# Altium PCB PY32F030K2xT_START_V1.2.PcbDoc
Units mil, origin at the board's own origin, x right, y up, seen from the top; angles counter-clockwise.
Board outline 1183.03 x 2496.24 mil, 2 copper layers (Top Layer, Bottom Layer); 35 components, 40 nets, 165 pads, 10 vias.
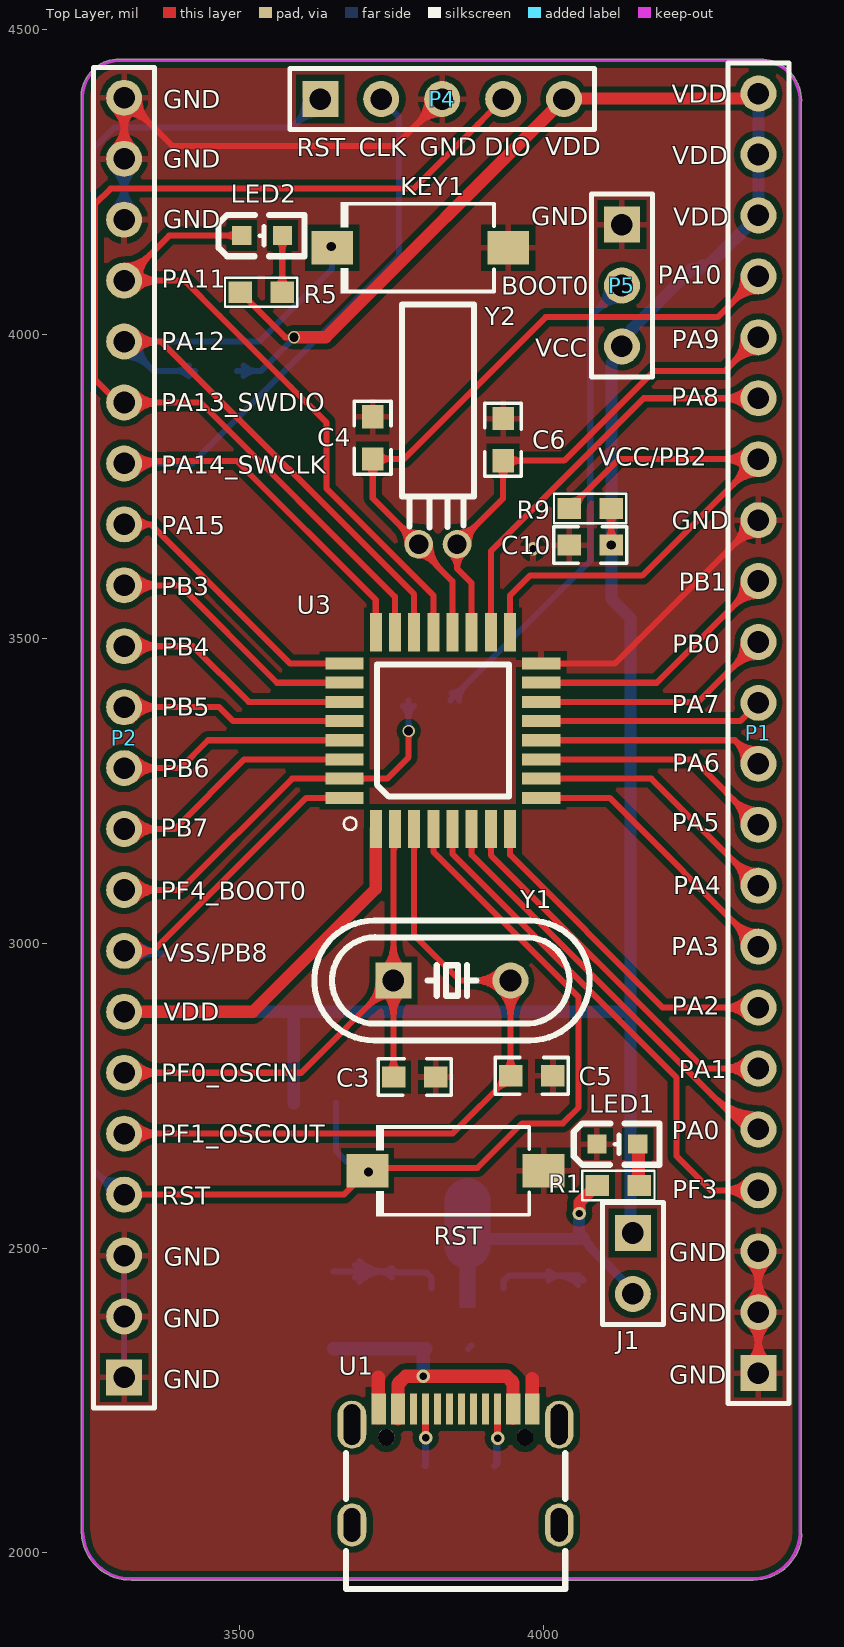
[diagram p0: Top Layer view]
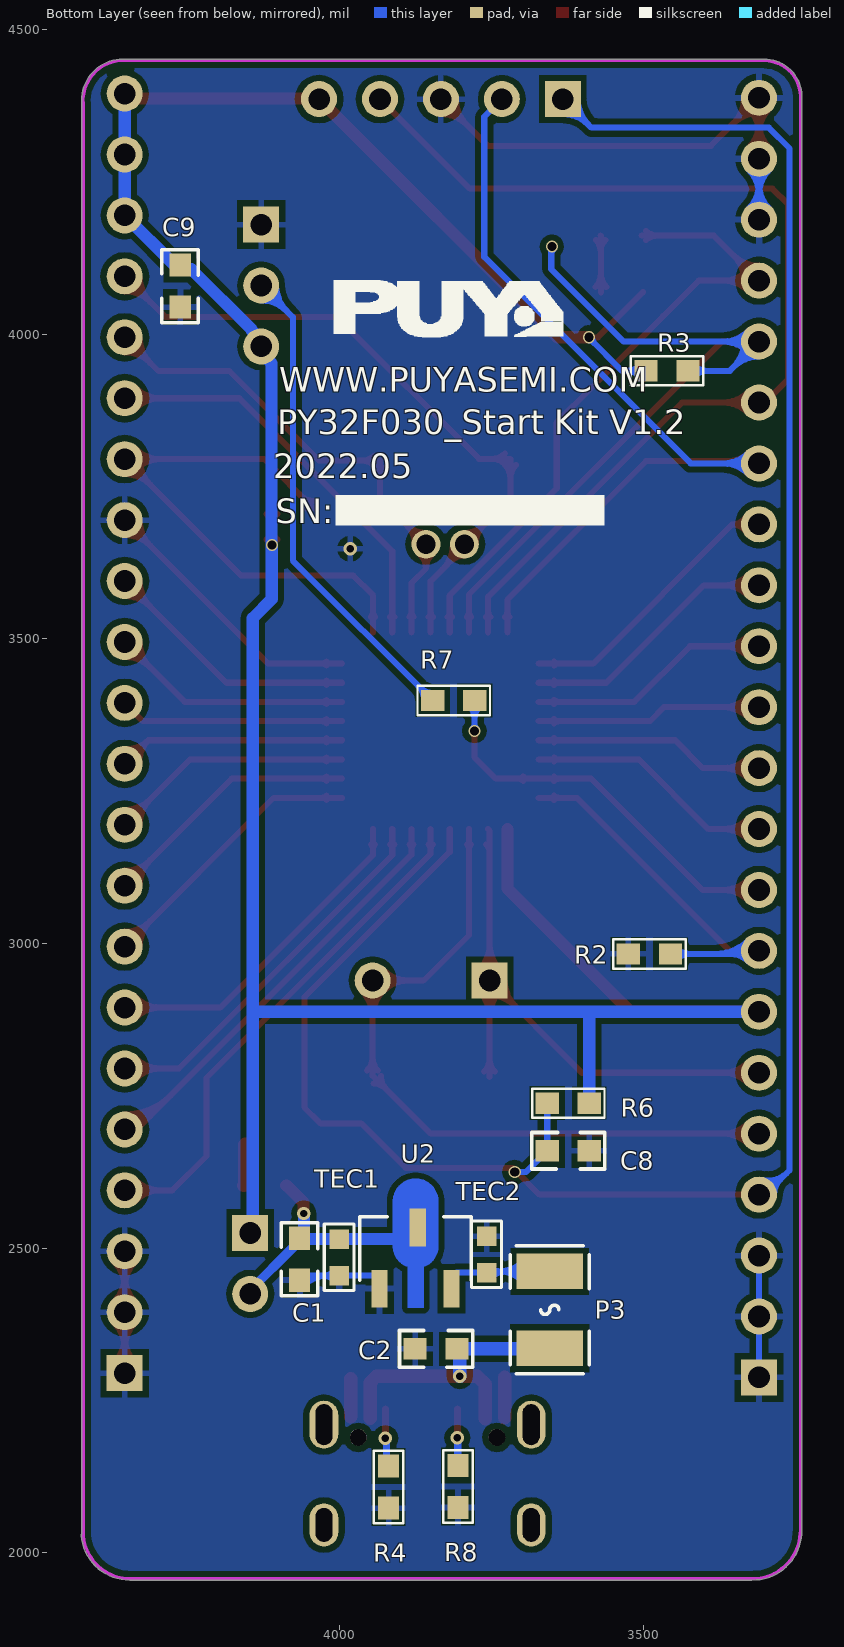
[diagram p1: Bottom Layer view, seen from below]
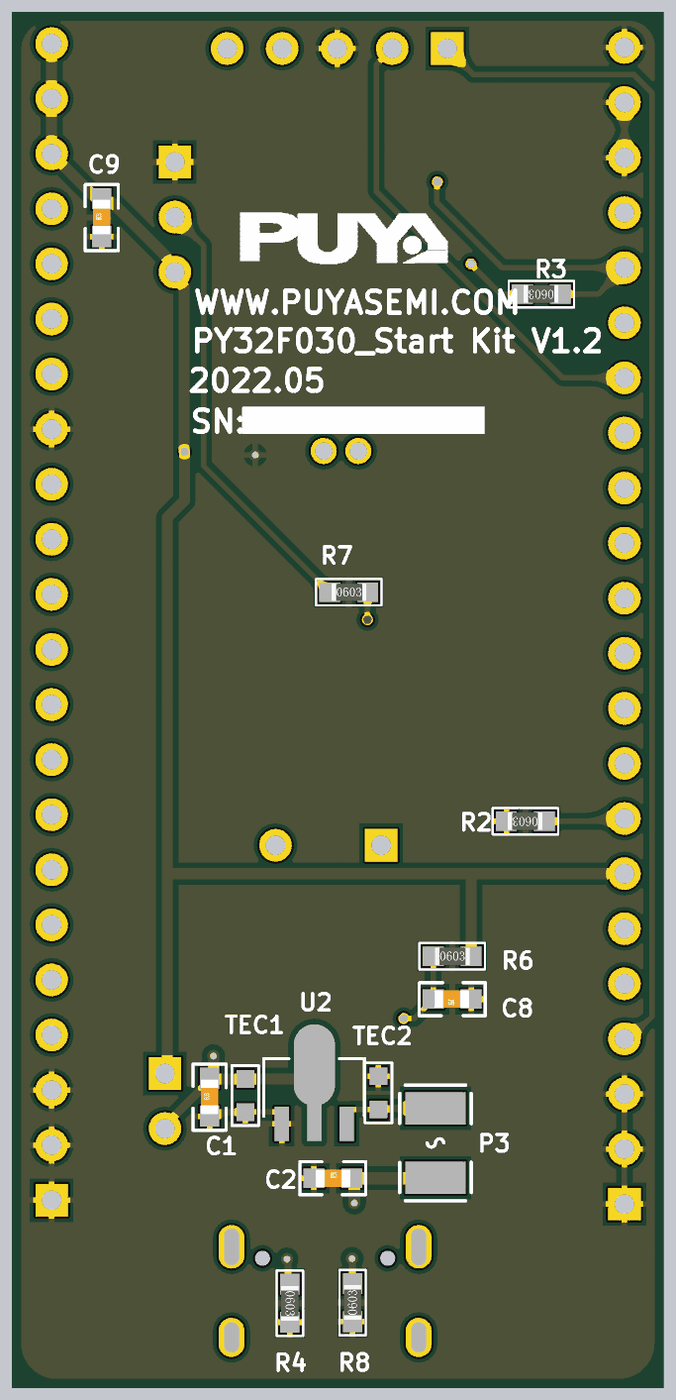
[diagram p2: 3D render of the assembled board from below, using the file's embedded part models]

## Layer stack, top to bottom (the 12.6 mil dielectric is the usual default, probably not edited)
Top Solder: solder mask 0.4, Solder Resist, Dk 3.5
Top Layer: signal copper 1.4
Dielectric1: dielectric 12.6, FR-4, Dk 4.8
Bottom Layer: signal copper 1.4
Bottom Solder: solder mask 0.4, Solder Resist, Dk 3.5

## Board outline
3240.49,4390 cw(c3243,4390) 3240.49,4390.02 3240.49,4391 cw(c3243,4391) 3240.51,4391.36 cw(c3302.5,4389.5) 3303.01,4451.52 cw(c3302.5,4389.5) 3303.02,4451.51 3303,4451.52 4360,4451.52 cw(c4360,4449) 4360.21,4451.51 cw(c4354.5,4383.5) 4422.75,4383.5 cw(c4354.5,4383.5) 4422.52,4377.9 4422.52,2031.01 cw(c4421,2029) 4423.52,2029 cw(c4421,2029) 4423.51,2028.79 cw(c4343.5,2035.5) 4336.9,1955.48 3323.21,1955.48 cw(c3323,1957.99) 3323.07,1955.48 cw(c3320.96,2035.24) 3241.27,2031.38 cw(c3243,2033.2) 3240.49,2033.2

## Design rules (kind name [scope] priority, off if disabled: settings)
Clearance Clearance_8 [InNamedPolygon('Bottom Layer-No Net')] p1: gap=10 ignorepadtopadclearanceinfootprint=FALSE
Clearance Clearance_7 [InNamedPolygon('Top Layer-No Net')] p2: gap=10 ignorepadtopadclearanceinfootprint=FALSE
Clearance Clearance_6 [InNamedPolygon('Bottom Layer-No Net')] p3: gap=10 ignorepadtopadclearanceinfootprint=FALSE
Clearance Clearance_5 [InNamedPolygon('Bottom Layer-No Net')] p4: gap=10 ignorepadtopadclearanceinfootprint=FALSE
Clearance Clearance_4 [InNamedPolygon('Bottom Layer-No Net')] p5: gap=15 ignorepadtopadclearanceinfootprint=FALSE
Clearance Clearance_3 [InNamedPolygon('Bottom Layer-No Net')] p6: gap=15 ignorepadtopadclearanceinfootprint=FALSE
Clearance Clearance_2 [InNamedPolygon('Bottom Layer-No Net')] p7: gap=10 ignorepadtopadclearanceinfootprint=FALSE
Clearance Clearance_1 [InNamedPolygon('Bottom Layer-No Net')] p8: gap=10 ignorepadtopadclearanceinfootprint=FALSE except(0: Arc-Hole Track-Hole SMDPad-Hole THPad-Hole Via-Hole Fill-Hole Poly-Hole Region-Hole Text-Hole)
Clearance [All] p9: gap=6 ignorepadtopadclearanceinfootprint=FALSE
MinimumSolderMaskSliver [All] p1: minsoldermaskwidth=0
PolygonConnect [All] p1: connectstyle=Relief reliefconductorwidth=10 reliefentries=4 polygonreliefangle="90 Angle" airgapwidth=10
RoutingVias [All] p1: holewidth=20 width=30 viastyle="Through Hole" minholewidth=5 minwidth=10 maxholewidth=28 maxwidth=50
SilkToSilkClearance [All] p1: silktosilkclearance=0
SilkToSolderMaskClearance SilkscreenOverComponentPads [IsPad] p1: minsilkscreentomaskgap=10 clearancetoexposedcopper=TRUE
SolderMaskExpansion [All] p1: expansion=4 istentingtop=FALSE
Width [All] p1: maxlimit=100 minlimit=10 preferedwidth=12
27 further rules are at their usual default settings.

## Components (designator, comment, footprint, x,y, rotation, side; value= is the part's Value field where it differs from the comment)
C1 "0.1uF/50V" 0603C 4065,2482 r90 bottom
C2 "0.1uF/50V" 0603C 3841,2335 r180 bottom value=2.2uF
C3 "22pF" 0603C 3788,2781 r180 top
C4 "12.5pF" 0603C 3719,3830 r270 top
C5 "22pF" 0603C 3980,2783 r0 top
C6 "12.5pF" 0603C 3933,3827 r90 top
C8 "0.1uF/50V" 0603C 3624,2660 r0 bottom value=2.2uF
C9 "0.1uF/50V" 0603C 4261,4079 r90 bottom value=2.2uF
C10 "0.1uF/50V" 0603C 4076,3654 r0 top value=2.2uF
J1 "JUMP" HDR1X2 4146,2525 r270 top
KEY1 "1TS002B-2600-5001" SW 3844,4143 r180 top
LED1 "RED" 0603_LED 4135,2670 r0 top
LED2 "GREEN" 0603_LED 3552,4161 r0 top
P1 "Header 22" HDR1X22 4352,2295 r90 top
P2 "Header 22" HDR1X22 3311,2288 r90 top
P3 "SMD1210P005TF" SDM1210P005TF 3676,2396 r90 bottom
P4 "Debug" HDR1X5 3633,4386 r0 top
P5 "Header 3" HDR1X3 4128,4180 r270 top
R1 "470Ω" 0603R 4122,2602 r0 top value=10K
R2 "0" 0603R 3491,2984 r0 bottom value=10K
R3 "1.5K" 0603R 3462,3941 r0 bottom value=10K
R4 "5.1K" 0603R 3920,2108 r270 bottom value=10K
R5 "680Ω" 0603R 3536,4068 r0 top value=10K
R6 "10K" 0603R 3624,2737 r180 bottom
R7 "10K" 0603R 3812,3398 r180 bottom
R8 "5.1K" 0603R 3804,2109 r90 bottom value=10K
R9 "0" 0603R 4076,3713 r0 top value=10K
RST "1TS002B-2600-5001" SW 3902,2628 r180 top
TEC1 "10uF" 0603 4000,2485 r90 bottom value=10uF/16V
TEC2 "10uF" 0603 3758,2490 r270 bottom value=10uF/16V
U1 "KH-TYPE-C-16P" USB-C-SMD_KH-TYPE-C-16P 3855,2141 r0 top
U2 "LM1117-3.3" LM1117-3.3 3933.9,2433.62 r270 bottom
U3 "PY32F030" LQFP32 3724,3188 r90 top
Y1 "24M" 25MHZ_2 3883,2936 r0 top value=X503225MSB2GI
Y2 "32.768KHz" 32768KHZ_2 3822,3779 r270 top value=X503225MSB2GI

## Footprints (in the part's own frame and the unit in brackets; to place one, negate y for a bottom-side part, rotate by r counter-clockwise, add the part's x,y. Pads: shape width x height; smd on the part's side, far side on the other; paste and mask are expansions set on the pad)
25MHZ_2 [mm]
  rect 1.5x1.5 hole 0.9: 1(-3.302,0.087)
  round 1.5 hole 0.9: 2(1.578,0.087)
  silkscreen extent -6.6,-2.41 4.88,2.59
0603 [mil]
  rect 32x32 smd: 1(30,0) 2(-30,0)
  silkscreen extent -54,-25 55,25
0603_LED [mil]
  rect 31.5x31.5 smd: 1(19,1) 2(-48,1)
  silkscreen extent -86,-33 55,35
0603C [mil]
  rect 38x35 smd: 1(-34.5,0) 2(34.5,0)
  silkscreen extent -60,-30 60,30, body extent -31,-16 32,16, height 12
0603R [mil]
  rect 38x35 smd: 1(-34.5,1) 2(34.5,1)
  silkscreen extent -59,-23 59,25, body extent -31,-15 32,17, height 18
32768KHZ_2 [mm]
  round 1.2 hole 0.8: 1(3.142,0.903) 2(3.142,-0.697)
  silkscreen extent -6.86,-1.4 2.44,1.6
HDR1X2 [mm] "Connector; Header; 2 Position"
  rect 1.5x1.5 hole 0.9: 1(0,0)
  round 1.5 hole 0.9: 2(2.54,0)
  silkscreen extent -1.27,-1.27 3.81,1.27
HDR1X3 [mm] "Connector; Header; 3 Position"
  rect 1.5x1.5 hole 0.9: 1(0,0)
  round 1.5 hole 0.9: 2(2.54,0) 3(5.08,0)
  silkscreen extent -1.27,-1.27 6.35,1.27
HDR1X5 [mm] "Connector; Header; 5 Position"
  rect 1.5x1.5 hole 0.9: 1(0,0)
  round 1.5 hole 0.9: 2(2.54,0) 3(5.08,0) 4(7.62,0) 5(10.16,0)
  silkscreen extent -1.27,-1.27 11.43,1.27
HDR1X22 [mm] "Connector; Header; 22 Position"
  rect 1.5x1.5 hole 0.9: 1(0,0)
  round 1.5 hole 0.9: 2(2.54,0) 3(5.08,0) 4(7.62,0) 5(10.16,0) 6(12.7,0) 7(15.24,0) 8(17.78,0) 9(20.32,0) 10(22.86,0) 11(25.4,0) 12(27.94,0) 13(30.48,0) 14(33.02,0) 15(35.56,0) 16(38.1,0) 17(40.64,0) 18(43.18,0) 19(45.72,0) 20(48.26,0) 21(50.8,0) 22(53.34,0)
  silkscreen extent -1.27,-1.27 54.61,1.27
LM1117-3.3 [mm]
  rect 1.575x0.672 smd: 1(0,0) 2(-2.55,1.598) 3(0,3)
  Top Layer region: -3.64,2.459 -1.785,2.459 -1.741,2.458 -1.696,2.455 -1.652,2.449 -1.608,2.442 -1.565,2.433 -1.522,2.421 -1.479,2.408 -1.437,2.393 -1.396,2.375 -1.356,2.356 -1.317,2.335 -1.279,2.312 -1.241,2.288 -1.206,2.261 -1.171,2.233 -1.138,2.204 -1.106,2.173 -1.075,2.14 -1.047,2.106 -1.019,2.071 -0.994,2.034 -0.97,1.996 -0.948,1.958 -0.928,1.918 -0.91,1.839 0.788,1.839 0.788,1.179 -0.91,1.179 -0.928,1.099 -0.948,1.06 -0.97,1.021 -0.994,0.983 -1.019,0.947 -1.047,0.911 -1.075,0.877 -1.106,0.845 -1.138,0.814 -1.171,0.784 -1.206,0.756 -1.241,0.73 -1.279,0.705 -1.317,0.682 -1.356,0.661 -1.396,0.642 -1.437,0.625 -1.479,0.609 -1.522,0.596 -1.565,0.585 -1.608,0.575 -1.652,0.568 -1.696,0.563 -1.741,0.56 -1.785,0.559 -3.64,0.559 -3.684,0.56 -3.728,0.563 -3.773,0.568 -3.817,0.575 -3.86,0.585 -3.903,0.596 -3.946,0.609 -3.988,0.625 -4.029,0.642 -4.069,0.661 -4.108,0.682 -4.146,0.705 -4.183,0.73 -4.219,0.756 -4.254,0.784 -4.287,0.814 -4.319,0.845 -4.349,0.877 -4.378,0.911 -4.405,0.947 -4.431,0.983 -4.455,1.021 -4.477,1.06 -4.497,1.099 -4.515,1.14 -4.531,1.181 -4.546,1.224 -4.558,1.266 -4.568,1.31 -4.577,1.353 -4.583,1.398 -4.587,1.442 -4.589,1.486 -4.589,1.531 -4.587,1.575 -4.583,1.62 -4.577,1.664 -4.568,1.708 -4.558,1.751 -4.546,1.794 -4.531,1.836 -4.515,1.877 -4.497,1.918 -4.477,1.958 -4.455,1.996 -4.431,2.034 -4.405,2.071 -4.378,2.106 -4.349,2.14 -4.319,2.173 -4.287,2.204 -4.254,2.233 -4.219,2.261 -4.183,2.288 -4.146,2.312 -4.108,2.335 -4.069,2.356 -4.029,2.375 -3.988,2.393 -3.946,2.408 -3.903,2.421 -3.86,2.433 -3.817,2.442 -3.773,2.449 -3.728,2.455 -3.684,2.458
  silkscreen extent -3.01,-0.83 -0.35,3.83
LQFP32 [mil]
  rect 63x19.7 smd: 1(0,0) 2(0,-31.5) 3(0,-63) 4(0,-94.5) 5(0,-125.9) 6(0,-157.4) 7(0,-188.9) 8(0,-220.4) 17(322.8,-220.4) 18(322.8,-188.9) 19(322.8,-157.4) 20(322.8,-125.9) 21(322.8,-94.5) 22(322.8,-63) 23(322.8,-31.5) 24(322.8,0)
  rect 19.7x63 smd: 9(51.2,-271.6) 10(82.7,-271.6) 11(114.2,-271.6) 12(145.7,-271.6) 13(177.1,-271.6) 14(208.6,-271.6) 15(240.1,-271.6) 16(271.6,-271.6) 25(271.6,51.2) 26(240.1,51.2) 27(208.6,51.2) 28(177.1,51.2) 29(145.7,51.2) 30(114.2,51.2) 31(82.7,51.2) 32(51.2,51.2)
  silkscreen extent -2,-218 270,52, body extent -15,-286 339,68, height 63
SDM1210P005TF [mm]
  rect 1.485x2.781 smd: 1(-1.524,-0.549) 2(1.676,-0.549)
  silkscreen extent -2.59,-2.2 2.74,1.1
SW [mm]
  rect 1.74x1.4 smd: 1(-2.476,0.024) 2(4.864,0.024)
  silkscreen extent -1.88,-1.88 4.5,1.93
USB-C-SMD_KH-TYPE-C-16P [mm] "https://item.szlcsc.com/747093.html"
  oval 1.2x2 hole 0.7 slot 1.7 at 90 deg: 1(-4.32,1.765) 2(4.32,1.765)
  oval 1.2x1.8 hole 0.7 slot 1.4 at 90 deg: 3(-4.32,-2.415) 4(4.32,-2.415)
  rect 0.3x1.3 smd: A1(-3.35,2.415) A4(-2.55,2.415) A5(-1.25,2.415) A6(-0.25,2.415) A7(0.25,2.415) A8(1.25,2.415) A9(2.55,2.415) A12(3.35,2.415) B1(3.05,2.415) B4(2.25,2.415) B5(1.75,2.415) B6(0.75,2.415) B7(-0.75,2.415) B8(-1.75,2.415) B9(-2.25,2.415) B12(-3.05,2.415)
  round 0.7 hole 0.7 unplated: ""(-2.89,1.235) ""(2.89,1.235)
  silkscreen extent -4.57,-5.08 4.57,0.57

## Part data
C1 C3 C4 C5 C6: library part Cap, "Capacitor"
C2 C8 C9 C10: library part CAP, "Capacitor"
KEY1 RST: BOM_JLCPCB Part Class="Extended Part", BOM_Manufacturer=HYP
LED1 LED2: library part PDI-E803_Dup1
P1 P2: "Header, 22-Pin"
P4: library part CON5
P5: "Header, 3-Pin"
R1 R2 R3 R5 R6 R7 R9: library part Res, "Resistor"
R4 R8: library part Res_1, "Resistor"
TEC1 TEC2: library part 贴片钽电容
U1: BOM_JLCPCB Part Class="Extended Part", BOM_Manufacturer="Shenzhen Kinghelm Elec"
Y1 Y2: library part CRYSTAL, "Crystal"

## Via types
v1: diameter 22, hole 12, Top Layer to Bottom Layer, tented both sides, 5 vias
v2: diameter 20, hole 15, Top Layer to Bottom Layer, 5 vias

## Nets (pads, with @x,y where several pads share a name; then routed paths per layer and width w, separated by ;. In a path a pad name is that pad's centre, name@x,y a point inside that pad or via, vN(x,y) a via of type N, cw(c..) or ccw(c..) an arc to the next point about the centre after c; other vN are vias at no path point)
BOOT0: P2.9 R7.2 U3.31 | length 920.7
  Top Layer w10: P2.9 3404,3088 3586.7,3270.7 U3.31 3742.7,3270.7 3778,3306 v2(3778,3349) ; P2.9@3321.27,3077.73 cw(c3346.07,3052.93) 3346.07,3088 cw(c3346.07,3123.07) P2.9@3321.27,3098.27 ; P2.9@3328.34,3070.66 cw(c3370.21,3028.79) 3370.21,3088 cw(c3370.21,3147.21) P2.9@3328.34,3105.34 ; U3.31@3647.72,3267.27 ccw(c3639.44,3258.99) 3639.44,3270.7 ccw(c3639.44,3282.41) U3.31@3647.72,3274.13 ; U3.31@3697.88,3267.27 cw(c3706.16,3258.99) 3706.16,3270.7 cw(c3706.16,3282.41) U3.31@3697.88,3274.13 ; v2@3774.46,3345.46 cw(c3765.93,3336.93) 3778,3336.93 cw(c3790.07,3336.93) v2@3781.54,3345.46
  Bottom Layer w10: R7.2@3768.66,3390.16 cw(c3746.12,3367.62) 3778,3367.62 ; v2@3774.46,3352.54 ccw(c3765.93,3361.07) 3778,3361.07 ccw(c3790.07,3361.07) v2@3781.54,3352.54 ; R7.2 3778,3398.5 v2(3778,3349) ; 3778,3370.03 cw(c3806.47,3370.03) R7.2@3786.34,3390.16
GND: C1.1 C2.1 C3.1 C4.1 C5.2 C6.2 C8.1 C9.1 C10.1 KEY1.1 LED1.2 P1.1 P1.2 P1.3 P1.15 P2.1 P2.2 P2.3 P2.20 P2.21 P2.22 P4.3 P5.1 R2.2 R4.2 R8.1 RST.1 TEC1.2 TEC2.2 U1.A1 U1.A12 U1.B1 U1.B12 U2.1 U3.16 | length 3682.9
  Top Layer w10: P2.21@3293.66,4305.34 ccw(c3251.79,4347.21) 3311,4347.21 ccw(c3370.21,4347.21) P2.21@3328.34,4305.34 ; P2.22@3293.66,4370.66 cw(c3251.79,4328.79) 3311,4328.79 cw(c3370.21,4328.79) P2.22@3328.34,4370.66 ; P2.21@3300.73,4298.27 ccw(c3275.93,4323.07) 3311,4323.07 ccw(c3346.07,4323.07) P2.21@3321.27,4298.27 ; P2.22@3300.73,4377.73 cw(c3275.93,4352.93) 3311,4352.93 cw(c3346.07,4352.93) P2.22@3321.27,4377.73 ; P2.21 P2.22 3390,4309 3756,4309 P4.3 ; P2.22@3311,4363.47 cw(c3311,4304.26) 3352.87,4346.13 cw(c3394.74,4388) P2.22@3335.53,4388 ; P2.22@3311,4373.47 cw(c3311,4338.4) 3335.8,4363.2 cw(c3360.6,4388) P2.22@3325.53,4388 ; P4.3@3808.47,4386 cw(c3749.26,4386) 3791.13,4344.13 cw(c3833,4302.26) P4.3@3833,4361.47 ; P4.3@3818.47,4386 cw(c3783.4,4386) 3808.2,4361.2 cw(c3833,4336.4) P4.3@3833,4371.47 ; U3.16 4116.6,3459.6 P1.15 ; U3.16@4020.68,3456.17 cw(c4028.96,3447.89) 4028.96,3459.6 cw(c4028.96,3471.31) U3.16@4020.68,3463.03 ; P1.15@4327.47,3695 cw(c4268.26,3695) 4310.13,3653.13 cw(c4352,3611.26) P1.15@4352,3670.47 ; P1.1@4334.66,2312.34 ccw(c4292.79,2354.21) 4352,2354.21 ccw(c4411.21,2354.21) P1.1@4369.34,2312.34 ; P1.2@4334.66,2377.66 cw(c4292.79,2335.79) 4352,2335.79 cw(c4411.21,2335.79) P1.2@4369.34,2377.66 ; P1.2@4334.66,2412.34 ccw(c4292.79,2454.21) 4352,2454.21 ccw(c4411.21,2454.21) P1.2@4369.34,2412.34 ; P1.3@4334.66,2477.66 cw(c4292.79,2435.79) 4352,2435.79 cw(c4411.21,2435.79) P1.3@4369.34,2477.66 ; P1.15@4337.47,3695 cw(c4302.4,3695) 4327.2,3670.2 cw(c4352,3645.4) P1.15@4352,3680.47 ; P1.1@4341.73,2305.27 ccw(c4316.93,2330.07) 4352,2330.07 ccw(c4387.07,2330.07) P1.1@4362.27,2305.27 ; P1.2@4341.73,2384.73 cw(c4316.93,2359.93) 4352,2359.93 cw(c4387.07,2359.93) P1.2@4362.27,2384.73 ; P1.2@4341.73,2405.27 ccw(c4316.93,2430.07) 4352,2430.07 ccw(c4387.07,2430.07) P1.2@4362.27,2405.27 ; P1.3@4341.73,2484.73 cw(c4316.93,2459.93) 4352,2459.93 cw(c4387.07,2459.93) P1.3@4362.27,2484.73 ; P1.1 P1.2 P1.3
  Top Layer w22: U1.A1@3728,2222 3728,2288 ; U1.A12@3981,2223 3981,2286
  Bottom Layer w10: P2.20@3293.66,4205.34 ccw(c3251.79,4247.21) 3311,4247.21 ccw(c3370.21,4247.21) P2.20@3328.34,4205.34 ; P2.21@3293.66,4270.66 cw(c3251.79,4228.79) 3311,4228.79 cw(c3370.21,4228.79) P2.21@3328.34,4270.66 ; P2.20@3300.73,4198.27 ccw(c3275.93,4223.07) 3311,4223.07 ccw(c3346.07,4223.07) P2.20@3321.27,4198.27 ; P2.21@3300.73,4277.73 cw(c3275.93,4252.93) 3311,4252.93 cw(c3346.07,4252.93) P2.21@3321.27,4277.73 ; P2.1@3311,2278 P2.3@3311,2478 ; P2.20 P2.21 ; R2.2@3522,2979.5 R2.2 ; C2.1 C2.1@3881,2340.5 ; U2.1 3933.9,2446.77 3942.13,2455 TEC1.2 4057.5,2455 C1.1 ; TEC1.2@4007.78,2447.22 cw(c4026.56,2428.44) 4026.56,2455 cw(c4026.56,2481.56) TEC1.2@4007.78,2462.78 ; 4020.34,2455 cw(c4020.34,2404.34) C1.1@4056.16,2440.16 ; 4044.48,2455 cw(c4044.48,2428.48) C1.1@4063.23,2447.23
  other v1: 3982,3648
MCU_RST: C8.2 P2.4 P4.1 R6.1 RST.2 U3.4 | length 3911.5
  Top Layer w10: P2.4 3671.47,2588 RST.2 ; v2(3712,2625) RST.2@3715.54,2625 ; RST.2@3712,2628.53 3715.47,2632 3891,2632 3964,2705 4031,2705 4057,2731 4057,2912 3818.5,3150.5 3818.5,3162.92 U3.4
  Bottom Layer w10: 3266,2623 ccw(c3295.63,2652.63) P2.4@3305.33,2611.86 ; 3276.2,2612.8 cw(c3251.4,2588) P2.4@3286.47,2588 ; 3278.66,2610.34 ccw(c3300.5,2632.18) P2.4@3307.64,2602.13 ; P2.4@3311,2578 3261,2628 3261,4305 3295,4339 3586,4339 P4.1 ; P4.1@3608.47,4386 cw(c3549.26,4386) 3591.13,4344.13 cw(c3633,4302.26) P4.1@3633,4361.47 ; P4.1@3618.47,4386 cw(c3583.4,4386) 3608.2,4361.2 cw(c3633,4336.4) P4.1@3633,4371.47 ; R6.1 C8.2 3693.5,2625 v2(3712,2625)
MCU_VDD: C9.2 C10.2 J1.1 P1.20 P1.21 P1.22 P2.7 P4.5 P5.3 R3.2 R5.1 R6.2 R9.2 U3.1 | length 4993
  Top Layer w10: R5.1 3575.5,3995 v2(3590,3995) ; C10.2@4101.66,3662.84 ccw(c4080.32,3684.18) 4110.5,3684.18 ccw(c4140.68,3684.18) C10.2@4119.34,3662.84 ; R9.2@4101.66,3705.16 cw(c4080.32,3683.82) 4110.5,3683.82 cw(c4140.68,3683.82) R9.2@4119.34,3705.16 ; C10.2@4106.96,3657.54 ccw(c4098.43,3666.07) 4110.5,3666.07 ccw(c4122.57,3666.07) C10.2@4114.04,3657.54 ; v2(4110.5,3654) R9.2
  Top Layer w20: P2.7 3522,2888 3724,3090 U3.1 ; v2(3590,3995) 3642,3995 P4.5 4034,4387 4333.43,4387 4341.43,4395 P1.22
  Bottom Layer w10: R3.2 3536,3940 3590,3994 v2(3590,3995) ; R3.2@3506.84,3931.16 cw(c3528.18,3909.82) 3528.18,3940 cw(c3528.18,3970.18) R3.2@3506.84,3948.84 ; 3580.76,3984.76 ccw(c3570.51,3995) v2@3585,3995 ; 3583.17,3987.17 cw(c3590,3980.34) v2@3590,3990 ; C9.2@4248.5,4101 4254.25,4106.75 C9.2@4255.25,4107.75 ; C9.2 C9.2@4270.5,4113.5
  Bottom Layer w20: P2.7 3589.5,2888 ; R6.2 3589.5,2888 ; J1.1@4142,2515 4142,2888 ; C9.2@4254.25,4106.75 4242.75,4106.75 4144.09,4008.09 4144.09,4006.66 4128,3990.57 P5.3 4128,3969.43 4111,3952.43 4111,3654.5 v2(4110.5,3654) 4110.67,3653.83 4110.67,3565.33 4142,3534 4142,2888 ; C9.2@4255.25,4107.75 C9.2 ; C9.2@4270.5,4113.5 P1.20 P1.21 P1.22 ; 3589.5,2888 4142,2888
NetC1_2: C1.2 J1.2 R1.1 TEC1.1 U2.2 | length 433.3
  Top Layer w20: v1(4058,2557) 4058.38,2557.38 4058.38,2575.38 4086,2603 R1.1
  Bottom Layer w15: C1.2 4065,2512 4068,2512 4075,2505 4075,2502 4146,2431 J1.2
  Bottom Layer w20: U2.2 3871,2518.23 3874.23,2515 TEC1.1 C1.2@4057.5,2515 ; v1(4058,2557) 4057.5,2556.5 4057.5,2524 C1.2
NetLED1_1: LED1.1 R1.2 | length 69
  Top Layer w22: LED1.1 4155.25,2669.75 4155.25,2604.25 R1.2
NetLED2_1: LED2.1 R5.2 | length 181.4
  Top Layer w10: R5.2@3561.66,4077.84 ccw(c3540.32,4099.18) 3570.5,4099.18 ccw(c3600.68,4099.18) R5.2@3579.34,4077.84 ; LED2.1@3563.4,4154.4 cw(c3546.26,4137.26) 3570.5,4137.26 ; R5.2 3570.5,4161.5 LED2.1 ; 3570.5,4134.84 cw(c3598.16,4134.84) LED2.1@3578.6,4154.4
NetP3_2: P3.2 TEC2.1 U2.3 | length 371.1
  Bottom Layer w10: P3.2 3756.02,2461.98 TEC2.1 3807.18,2460 3815.79,2451.39 U2.3 ; P3.2@3689.97,2451.92 cw(c3714.27,2427.62) 3714.27,2461.98 cw(c3714.27,2496.34) P3.2@3689.97,2472.05 ; P3.2@3697.04,2444.85 cw(c3738.41,2403.48) 3738.41,2461.98 cw(c3738.41,2520.49) P3.2@3697.04,2479.12 ; 3726.65,2461.98 cw(c3726.65,2428.65) TEC2.1@3750.22,2452.22 ; 3736.23,2461.98 ccw(c3736.23,2481.77) TEC2.1@3750.22,2467.78
NetP5_2: P5.2 R7.1 | length 993.1
  Bottom Layer w10: R7.1 4076,3628.5 4076,4028 P5.2 ; R7.1@3848,3411.5 ccw(c3848,3438.06) 3866.78,3419.28 ; R7.1@3860.5,3399 cw(c3894.3,3399) 3870.4,3422.9 ; P5.2@4103.47,4080 cw(c4044.26,4080) 4086.13,4038.13 cw(c4128,3996.26) P5.2@4128,4055.47 ; P5.2@4113.47,4080 cw(c4078.4,4080) 4103.2,4055.2 cw(c4128,4030.4) P5.2@4128,4065.47
NetR4_1: R4.1 U1.B5 | length 98.9
  Top Layer w12: U1.B5 3923.9,2188.21 3924,2188.11 v1@3924,2185
  Bottom Layer w12: R4.1 3922.42,2145.92 3922.42,2186.2 v1(3924.33,2188.11)
NetR8_2: R8.2 U1.A5 | length 93.1
  Top Layer w10: v1@3805.79,2189.21 v1(3806,2189)
  Top Layer w12: v1@3805.79,2189.21 U1.A5
  Bottom Layer w12: R8.2 3805.5,2144 3805.5,2188.5 v1(3806,2189)
OSC32IN: C4.2 P1.19 U3.20 Y2.2 | length 1519.5
  Top Layer w10: C4.2@3710.16,3785.16 cw(c3688.82,3763.82) 3719,3763.82 cw(c3749.18,3763.82) C4.2@3727.84,3785.16 ; C4.2@3727.84,3786.66 cw(c3749.18,3765.32) 3749.18,3795.5 cw(c3749.18,3825.68) C4.2@3727.84,3804.34 ; Y2.2@3775.93,3655.3 ccw(c3730.97,3655.3) 3762.76,3687.09 ccw(c3794.55,3718.88) Y2.2@3794.55,3673.92 ; Y2.2@3794.55,3636.68 cw(c3794.55,3604.12) 3817.57,3627.14 ; Y2.2@3794.55,3650.16 3849.9,3594.82 U3.20 ; Y2.2 3719,3730.85 C4.2 3770.5,3795.5 4003,4028 4285,4028 P1.19 ; Y2.2@3803.17,3655.3 ccw(c3836.39,3655.3) 3812.9,3631.81 ; Y2.2@3813.17,3655.3 ccw(c3870.53,3655.3) 3829.97,3614.74 ; U3.20@3846.47,3535.88 ccw(c3838.19,3544.16) 3849.9,3544.16 ccw(c3861.61,3544.16) U3.20@3853.33,3535.88 ; P1.19@4327.47,4095 cw(c4268.26,4095) 4310.13,4053.13 cw(c4352,4011.26) P1.19@4352,4070.47 ; P1.19@4337.47,4095 cw(c4302.4,4095) 4327.2,4070.2 cw(c4352,4045.4) P1.19@4352,4080.47
OSC32OUT: C6.1 P1.18 U3.19 Y2.1 | length 1215.9
  Top Layer w10: Y2.1@3845.6,3641.01 cw(c3824.23,3615.46) 3857.54,3615.46 ; Y2.1@3857.54,3673.92 ccw(c3857.54,3718.88) 3889.33,3687.09 ccw(c3921.12,3655.3) Y2.1@3876.17,3655.3 ; Y2.1@3869.49,3641.01 ccw(c3890.86,3615.46) 3857.54,3615.46 ; U3.19@3877.97,3535.88 ccw(c3869.69,3544.16) 3881.4,3544.16 ccw(c3893.11,3544.16) U3.19@3884.83,3535.88 ; U3.19 3881.4,3591.6 3857.54,3615.46 ; C6.1@3924.16,3782.16 cw(c3902.82,3760.82) 3933,3760.82 cw(c3963.18,3760.82) C6.1@3941.84,3782.16 ; C6.1@3941.84,3783.66 cw(c3963.18,3762.32) 3963.18,3792.5 cw(c3963.18,3822.68) C6.1@3941.84,3801.34 ; P1.18@4327.47,3995 cw(c4268.26,3995) 4310.13,3953.13 cw(c4352,3911.26) P1.18@4352,3970.47 ; P1.18@4337.47,3995 cw(c4302.4,3995) 4327.2,3970.2 cw(c4352,3945.4) P1.18@4352,3980.47 ; P1.18 4296.53,3939.53 4180.03,3939.53 4033,3792.5 C6.1 3933,3730.76 Y2.1 3857.54,3615.46
OSCIN: C3.2 P2.6 U3.2 Y1.1 | length 1568.7
  Top Layer w10: P2.6 3601.59,2788 Y1.1 ; P2.6@3321.27,2777.73 cw(c3346.07,2752.93) 3346.07,2788 cw(c3346.07,2823.07) P2.6@3321.27,2798.27 ; P2.6@3328.34,2770.66 cw(c3370.21,2728.79) 3370.21,2788 cw(c3370.21,2847.21) P2.6@3328.34,2805.34 ; Y1.1@3728.21,2914.62 ccw(c3703.41,2939.43) Y1.1@3738.49,2939.43 ; Y1.1@3728.21,2914.63 cw(c3753.01,2889.82) Y1.1@3753.01,2924.9 ; Y1.1@3728.49,2939.43 cw(c3669.27,2939.43) 3711.14,2897.55 cw(c3753.01,2855.68) Y1.1@3753.01,2914.9 ; Y1.1@3735.67,2922.08 cw(c3693.8,2880.21) 3753.01,2880.21 cw(c3812.23,2880.21) Y1.1@3770.36,2922.08 ; Y1.1@3735.67,2956.77 ccw(c3693.8,2998.64) 3753.01,2998.64 ccw(c3812.23,2998.64) Y1.1@3770.36,2956.77 ; Y1.1@3742.74,2929.15 cw(c3717.94,2904.35) 3753.01,2904.35 cw(c3788.09,2904.35) Y1.1@3763.29,2929.15 ; Y1.1@3742.74,2949.7 ccw(c3717.94,2974.5) 3753.01,2974.5 ccw(c3788.09,2974.5) Y1.1@3763.29,2949.7 ; C3.2@3744.66,2789.84 ccw(c3724.5,2810) 3753.01,2810 ; 3753.01,2812.35 ccw(c3784.85,2812.35) C3.2@3762.34,2789.84 ; 3753.01,3148.64 cw(c3773.21,3148.64) U3.2@3758.93,3162.92 ; C3.2 3753.01,2781.49 Y1.1 ; U3.2 3753.01,3185.51 Y1.1
OSCOUT: C5.1 P2.5 U3.3 Y1.2 | length 1750.8
  Top Layer w10: P2.5 3849.78,2688 C5.1@3945.14,2783.36 ; P2.5@3321.27,2677.73 cw(c3346.07,2652.93) 3346.07,2688 cw(c3346.07,2723.07) P2.5@3321.27,2698.27 ; P2.5@3328.34,2670.66 cw(c3370.21,2628.79) 3370.21,2688 cw(c3370.21,2747.21) P2.5@3328.34,2705.34 ; U3.3@3783.57,3162.92 cw(c3775.29,3154.64) 3787,3154.64 cw(c3798.71,3154.64) U3.3@3790.43,3162.92 ; U3.3 3787,3014 3861.57,2939.43 Y1.2 C5.1@3945.14,2783.36 ; 3922.11,2760.33 ccw(c3899.44,2783) C5.1@3931.5,2783 ; 3923.99,2762.21 cw(c3944,2742.2) C5.1@3944,2770.5 ; Y1.2@3927.8,2956.77 cw(c3885.93,2998.64) 3885.93,2939.43 cw(c3885.93,2880.21) 3927.8,2922.08 cw(c3885.93,2880.21) 3945.14,2880.21 cw(c4004.35,2880.21) Y1.2@3962.48,2922.08 ; Y1.2@3934.87,2949.7 cw(c3910.07,2974.5) 3910.07,2939.42 cw(c3910.07,2904.35) 3934.87,2929.15 cw(c3910.07,2904.35) 3945.14,2904.35 cw(c3980.21,2904.35) Y1.2@3955.41,2929.15 ; C5.1@3936.66,2791.84 ccw(c3916.19,2812.31) 3945.14,2812.31 ; 3945.14,2814.05 ccw(c3976.55,2814.05) C5.1@3954.34,2791.84 ; C5.1 C5.1@3945.14,2783.36
PA0: P1.5 U3.6 | length 914.4
  Top Layer w10: U3.6@3877.97,3162.92 cw(c3869.69,3154.64) 3881.4,3154.64 cw(c3893.11,3154.64) U3.6@3884.83,3162.92 ; U3.6 3881.4,3145.6 4332,2695 P1.5 ; 4275.99,2751.01 ccw(c4352,2827.03) P1.5@4352,2719.53 ; 4293.06,2733.94 ccw(c4352,2792.88) P1.5@4352,2709.53 ; 4310.13,2716.87 ccw(c4352,2758.74) P1.5@4352,2699.53
PA1: P1.6 U3.7 | length 793.5
  Top Layer w10: U3.7@3909.47,3162.92 cw(c3901.19,3154.64) 3912.9,3154.64 cw(c3924.61,3154.64) U3.7@3916.33,3162.92 ; U3.7 3912.9,3145.1 4263,2795 P1.6 ; P1.6@4334.66,2777.66 ccw(c4292.79,2735.79) 4292.79,2795 ccw(c4292.79,2854.21) P1.6@4334.66,2812.34 ; P1.6@4341.73,2784.73 ccw(c4316.93,2759.93) 4316.93,2795 ccw(c4316.93,2830.07) P1.6@4341.73,2805.27
PA2: P1.7 U3.8 | length 720.3
  Top Layer w10: U3.8@3940.97,3162.92 cw(c3932.69,3154.64) 3944.4,3154.64 cw(c3956.11,3154.64) U3.8@3947.83,3162.92 ; U3.8 3944.4,3145.6 4195,2895 P1.7 ; P1.7@4334.66,2877.66 ccw(c4292.79,2835.79) 4292.79,2895 ccw(c4292.79,2954.21) P1.7@4334.66,2912.34 ; P1.7@4341.73,2884.73 ccw(c4316.93,2859.93) 4316.93,2895 ccw(c4316.93,2930.07) P1.7@4341.73,2905.27
PA3: P1.8 U3.9 | length 624
  Top Layer w10: U3.9 4107.8,3239.2 P1.8 ; U3.9@4020.68,3235.77 cw(c4028.96,3227.49) 4028.96,3239.2 cw(c4028.96,3250.91) U3.9@4020.68,3242.63 ; P1.8@4327.47,2995 ccw(c4268.26,2995) 4310.13,3036.87 ccw(c4352,3078.74) P1.8@4352,3019.53 ; P1.8@4337.47,2995 ccw(c4302.4,2995) 4327.2,3019.8 ccw(c4352,3044.6) P1.8@4352,3009.53
PA4: P1.9 U3.10 | length 595.7
  Top Layer w10: U3.10 4176.3,3270.7 P1.9 ; U3.10@4020.68,3267.27 cw(c4028.96,3258.99) 4028.96,3270.7 cw(c4028.96,3282.41) U3.10@4020.68,3274.13 ; P1.9@4327.47,3095 ccw(c4268.26,3095) 4310.13,3136.87 ccw(c4352,3178.74) P1.9@4352,3119.53 ; P1.9@4337.47,3095 ccw(c4302.4,3095) 4327.2,3119.8 ccw(c4352,3144.6) P1.9@4352,3109.53
PA5: P1.10 U3.11 | length 567.3
  Top Layer w10: U3.11 4244.8,3302.2 P1.10 ; U3.11@4020.68,3298.77 cw(c4028.96,3290.49) 4028.96,3302.2 cw(c4028.96,3313.91) U3.11@4020.68,3305.63 ; P1.10@4327.47,3195 ccw(c4268.26,3195) 4310.13,3236.87 ccw(c4352,3278.74) P1.10@4352,3219.53 ; P1.10@4337.47,3195 ccw(c4302.4,3195) 4327.2,3219.8 ccw(c4352,3244.6) P1.10@4352,3209.53
PA6: P1.11 U3.12 | length 521.8
  Top Layer w10: U3.12 4313.3,3333.7 ; U3.12@4020.68,3330.27 cw(c4028.96,3321.99) 4028.96,3333.7 cw(c4028.96,3345.41) U3.12@4020.68,3337.13 ; P1.11@4327.51,3296.4 ccw(c4278.8,3299.2) 4313.3,3333.7 ; P1.11@4337.5,3295.83 ccw(c4308.65,3297.49) 4329.08,3317.92 ccw(c4349.51,3338.35) P1.11@4351.17,3309.5 ; P1.11@4350.6,3319.49 cw(c4347.8,3368.2) 4313.3,3333.7 ; P1.11 4313.3,3333.7
PA7: P1.12 U3.13 | length 387.2
  Top Layer w10: U3.13 4322.1,3365.1 P1.12 ; U3.13@4020.68,3361.67 cw(c4028.96,3353.39) 4028.96,3365.1 cw(c4028.96,3376.81) U3.13@4020.68,3368.53
PA8: P1.17 U3.18 | length 842.8
  Top Layer w10: U3.18@3909.47,3535.88 ccw(c3901.19,3544.16) 3912.9,3544.16 ccw(c3924.61,3544.16) U3.18@3916.33,3535.88 ; U3.18 3912.9,3644.11 4163.79,3895 P1.17 ; P1.17@4334.66,3877.66 ccw(c4292.79,3835.79) 4292.79,3895 ccw(c4292.79,3954.21) P1.17@4334.66,3912.34 ; P1.17@4341.73,3884.73 ccw(c4316.93,3859.93) 4316.93,3895 ccw(c4316.93,3930.07) P1.17@4341.73,3905.27
PA11: LED2.2 P2.19 U3.21 | length 1428.8
  Top Layer w10: P2.19@3303,4086 P2.19@3306,4083 ; P2.19@3311,4102.53 ccw(c3311,4137.6) 3335.8,4112.8 ccw(c3360.6,4088) P2.19@3325.53,4088 ; P2.19@3311,4112.53 ccw(c3311,4171.74) 3352.87,4129.87 ccw(c3394.74,4088) P2.19@3335.53,4088 ; P2.19@3321.27,4077.73 cw(c3346.07,4052.93) 3346.07,4088 cw(c3346.07,4123.07) P2.19@3321.27,4098.27 ; P2.19@3328.34,4070.66 cw(c3370.21,4028.79) 3370.21,4088 cw(c3370.21,4147.21) P2.19@3328.34,4105.34 ; LED2.2@3496.4,4154.4 ccw(c3478.05,4136.05) 3478.05,4162 ccw(c3478.05,4187.95) LED2.2@3496.4,4169.6 ; LED2.2 3385,4162 P2.19 3321,4088 3410.21,4088 3468.41,4029.8 3584.8,3913.41 3643,3855.21 3643,3747 3818.5,3571.5 U3.21 ; U3.21@3815.07,3535.88 ccw(c3806.79,3544.16) 3818.5,3544.16 ccw(c3830.21,3544.16) U3.21@3821.93,3535.88
PA12: KEY1.2 P2.18 R3.1 U3.22 | length 1796.5
  Top Layer w10: P2.18 3372,3988 3787,3573 U3.22 ; P2.18@3321.27,3977.73 cw(c3346.07,3952.93) 3346.07,3988 cw(c3346.07,4023.07) P2.18@3321.27,3998.27 ; P2.18@3328.34,3970.66 cw(c3370.21,3928.79) 3370.21,3988 cw(c3370.21,4047.21) P2.18@3328.34,4005.34 ; U3.22@3783.57,3535.88 ccw(c3775.29,3544.16) 3787,3544.16 ccw(c3798.71,3544.16) U3.22@3790.43,3535.88
  Bottom Layer w10: P2.18@3311,3963.47 cw(c3311,3904.26) 3352.87,3946.13 cw(c3394.74,3988) P2.18@3335.53,3988 ; P2.18@3311,3973.47 cw(c3311,3938.4) 3335.8,3963.2 cw(c3360.6,3988) P2.18@3325.53,3988 ; P2.18@3321.27,3977.73 cw(c3346.07,3952.93) 3346.07,3988 cw(c3346.07,4023.07) P2.18@3321.27,3998.27 ; P2.18@3328.34,3970.66 cw(c3370.21,3928.79) 3370.21,3988 cw(c3370.21,4047.21) P2.18@3328.34,4005.34 ; R3.1@3417.16,3931.16 ccw(c3395.82,3909.82) 3395.82,3940 ccw(c3395.82,3970.18) R3.1@3417.16,3948.84 ; R3.1 3359,3940 P2.18 3533,3988 3652,4107 3652,4143 v2(3651,4144) ; v2@3647.46,4140.46 cw(c3636.51,4129.51) 3652,4129.51
PA15: P2.15 U3.25 | length 554.1
  Top Layer w10: P2.15@3331.86,3675.1 cw(c3355,3660.8) 3355,3688 ; P2.15@3331.86,3700.9 ccw(c3355,3715.2) 3355,3688 ; P2.15@3335,3688 P2.15 3355,3688 ; U3.25@3647.72,3456.17 ccw(c3639.44,3447.89) 3639.44,3459.6 ccw(c3639.44,3471.31) U3.25@3647.72,3463.03 ; U3.25 3583.4,3459.6 3355,3688
PB0: P1.13 U3.14 | length 563.7
  Top Layer w10: U3.14 4253.6,3396.6 P1.13 ; U3.14@4020.68,3393.17 cw(c4028.96,3384.89) 4028.96,3396.6 cw(c4028.96,3408.31) U3.14@4020.68,3400.03 ; P1.13@4327.47,3495 cw(c4268.26,3495) 4310.13,3453.13 cw(c4352,3411.26) P1.13@4352,3470.47 ; P1.13@4337.47,3495 cw(c4302.4,3495) 4327.2,3470.2 cw(c4352,3445.4) P1.13@4352,3480.47
PB1: P1.14 U3.15 | length 592
  Top Layer w10: U3.15 4185.1,3428.1 P1.14 ; U3.15@4020.68,3424.67 cw(c4028.96,3416.39) 4028.96,3428.1 cw(c4028.96,3439.81) U3.15@4020.68,3431.53 ; P1.14@4327.47,3595 cw(c4268.26,3595) 4310.13,3553.13 cw(c4352,3511.26) P1.14@4352,3570.47 ; P1.14@4337.47,3595 cw(c4302.4,3595) 4327.2,3570.2 cw(c4352,3545.4) P1.14@4352,3580.47
PB3: P2.14 U3.26 | length 594.5
  Top Layer w10: P2.14 3402,3588 3561.9,3428.1 U3.26 ; P2.14@3321.27,3577.73 cw(c3346.07,3552.93) 3346.07,3588 cw(c3346.07,3623.07) P2.14@3321.27,3598.27 ; P2.14@3328.34,3570.66 cw(c3370.21,3528.79) 3370.21,3588 cw(c3370.21,3647.21) P2.14@3328.34,3605.34 ; U3.26@3647.72,3424.67 ccw(c3639.44,3416.39) 3639.44,3428.1 ccw(c3639.44,3439.81) U3.26@3647.72,3431.53
PB4: P2.13 U3.27 | length 581.8
  Top Layer w10: P2.13 3424,3488 3515.4,3396.6 3543,3396.6 ; P2.13@3321.27,3477.73 cw(c3346.07,3452.93) 3346.07,3488 cw(c3346.07,3523.07) P2.13@3321.27,3498.27 ; P2.13@3328.34,3470.66 cw(c3370.21,3428.79) 3370.21,3488 cw(c3370.21,3547.21) P2.13@3328.34,3505.34 ; 3527.4,3396.6 3543,3396.6 ; U3.27@3647.72,3393.17 ccw(c3639.44,3384.89) 3639.44,3396.6 ccw(c3639.44,3408.31) U3.27@3647.72,3400.03 ; U3.27 3543,3396.6
PB5: P2.12 U3.28 | length 556
  Top Layer w10: P2.12@3311,3378 P2.12@3323.9,3365.1 ; P2.12 3467,3388 3489.9,3365.1 U3.28 ; P2.12@3321.27,3377.73 cw(c3346.07,3352.93) 3346.07,3388 cw(c3346.07,3423.07) P2.12@3321.27,3398.27 ; P2.12@3328.34,3370.66 cw(c3370.21,3328.79) 3370.21,3388 cw(c3370.21,3447.21) P2.12@3328.34,3405.34 ; U3.28@3647.72,3361.67 ccw(c3639.44,3353.39) 3639.44,3365.1 ccw(c3639.44,3376.81) U3.28@3647.72,3368.53
PB6: P2.11 U3.29 | length 547.2
  Top Layer w10: P2.11 3403,3288 3448.7,3333.7 U3.29 ; P2.11@3321.27,3277.73 cw(c3346.07,3252.93) 3346.07,3288 cw(c3346.07,3323.07) P2.11@3321.27,3298.27 ; P2.11@3328.34,3270.66 cw(c3370.21,3228.79) 3370.21,3288 cw(c3370.21,3347.21) P2.11@3328.34,3305.34 ; U3.29@3647.72,3330.27 ccw(c3639.44,3321.99) 3639.44,3333.7 ccw(c3639.44,3345.41) U3.29@3647.72,3337.13
PB7: P2.10 U3.30 | length 575.6
  Top Layer w10: P2.10 3394,3188 3508.2,3302.2 U3.30 ; P2.10@3321.27,3177.73 cw(c3346.07,3152.93) 3346.07,3188 cw(c3346.07,3223.07) P2.10@3321.27,3198.27 ; P2.10@3328.34,3170.66 cw(c3370.21,3128.79) 3370.21,3188 cw(c3370.21,3247.21) P2.10@3328.34,3205.34 ; U3.30@3647.72,3298.77 ccw(c3639.44,3290.49) 3639.44,3302.2 ccw(c3639.44,3313.91) U3.30@3647.72,3305.63
PF3: P1.4 U3.5 | length 1013.2
  Top Layer w10: U3.5@3846.47,3162.92 cw(c3838.19,3154.64) 3849.9,3154.64 cw(c3861.61,3154.64) U3.5@3853.33,3162.92 ; U3.5 3849.9,3147.38 4217.75,2779.54 4217.75,2651.25 4274,2595 P1.4 ; P1.4@4334.66,2577.66 ccw(c4292.79,2535.79) 4292.79,2595 ccw(c4292.79,2654.21) P1.4@4334.66,2612.34 ; P1.4@4341.73,2584.73 ccw(c4316.93,2559.93) 4316.93,2595 ccw(c4316.93,2630.07) P1.4@4341.73,2605.27
SWCLK: P2.16 P4.2 U3.24 | length 1722.5
  Top Layer w10: P2.16 3315,3792 3496,3792 3724,3564 U3.24 ; P2.16@3321.27,3777.73 cw(c3355.73,3743.27) 3355.73,3792 ; P2.16@3328.34,3770.66 cw(c3379.87,3719.13) 3379.87,3792 ; P2.16@3328.34,3805.34 ccw(c3360.56,3837.56) 3360.56,3792 ; U3.24@3720.57,3535.88 ccw(c3712.29,3544.16) 3724,3544.16 ccw(c3735.71,3544.16) U3.24@3727.43,3535.88
  Bottom Layer w10: P2.16 3423,3788 3762,4127 3762,4357 P4.2 ; P2.16@3321.27,3777.73 cw(c3346.07,3752.93) 3346.07,3788 cw(c3346.07,3823.07) P2.16@3321.27,3798.27 ; P2.16@3328.34,3770.66 cw(c3370.21,3728.79) 3370.21,3788 cw(c3370.21,3847.21) P2.16@3328.34,3805.34
SWDIO: P2.17 P4.4 U3.23 | length 1898.2
  Top Layer w10: P2.17@3311,3878 3263,3926 3263,4213 3289,4239 3786,4239 3891.13,4344.13 3908.2,4361.2 P4.4 ; P2.17 3437,3888 3755.5,3569.5 U3.23 ; P2.17@3321.27,3877.73 cw(c3346.07,3852.93) 3346.07,3888 cw(c3346.07,3923.07) P2.17@3321.27,3898.27 ; P2.17@3328.34,3870.66 cw(c3370.21,3828.79) 3370.21,3888 cw(c3370.21,3947.21) P2.17@3328.34,3905.34 ; U3.23@3752.07,3535.88 ccw(c3743.79,3544.16) 3755.5,3544.16 ccw(c3767.21,3544.16) U3.23@3758.93,3535.88
Type_C: C2.2 P3.1 U1.A4 U1.A9 U1.B4 U1.B9 | length 513.7
  Top Layer w22: U1.A4@3760.5,2220 3760.5,2277.15 3773.39,2290.04 3938.96,2290.04 3949.3,2279.7 U1.B4@3949.3,2221
  Bottom Layer w20: P3.1 P3.1@3655.39,2335
  Bottom Layer w22: P3.1@3655.39,2335 C2.2 3802,2330.5 v1(3802,2290)
VCC/PB2: P1.16 R9.1 U3.17 | length 1266.9
  Top Layer w10: U3.17@3940.97,3535.88 ccw(c3932.69,3544.16) 3944.4,3544.16 ccw(c3956.11,3544.16) U3.17@3947.83,3535.88 ; U3.17 3944.4,3571.4 3977,3604 4161,3604 P1.16 4122.5,3795 R9.1 ; R9.1@4043,3726.5 ccw(c4043,3753.06) 4061.78,3734.28 ; R9.1@4055.5,3714 cw(c4089.3,3714) 4065.4,3737.9 ; P1.16@4327.47,3795 cw(c4268.26,3795) 4310.13,3753.13 cw(c4352,3711.26) P1.16@4352,3770.47 ; P1.16@4334.66,3777.66 ccw(c4292.79,3735.79) 4292.79,3795 ccw(c4292.79,3854.21) P1.16@4334.66,3812.34 ; P1.16@4337.47,3795 cw(c4302.4,3795) 4327.2,3770.2 cw(c4352,3745.4) P1.16@4352,3780.47 ; P1.16@4341.73,3784.73 ccw(c4316.93,3759.93) 4316.93,3795 ccw(c4316.93,3830.07) P1.16@4341.73,3805.27
VSS/PB8: P2.8 R2.1 U3.32 | length 901.8
  Top Layer w10: P2.8@3330.88,2973.63 cw(c3359,2953.3) 3359,2988 ; P2.8@3330.88,3002.37 ccw(c3359,3022.7) 3359,2988 ; P2.8@3334,2988 P2.8 3359,2988 ; U3.32@3647.72,3235.77 ccw(c3639.44,3227.49) 3639.44,3239.2 ccw(c3639.44,3250.91) U3.32@3647.72,3242.63 ; U3.32 3610.2,3239.2 3359,2988
  Bottom Layer w10: P2.8 3316,2983 R2.1 ; P2.8@3321.27,2998.27 ccw(c3358.14,3035.14) 3358.14,2983 ccw(c3358.14,2940.86) P2.8@3328.34,2970.66 ; P2.8@3328.34,3005.34 ccw(c3382.29,3059.29) 3382.29,2983 ; R2.1@3446.16,2974.16 ccw(c3424.82,2952.82) 3424.82,2983 ccw(c3424.82,3013.18) R2.1@3446.16,2991.84
pads on no net: U1. U1.1 U1.2 U1.3 U1.4 U1.A6 U1.A7 U1.A8 U1.B6 U1.B7 U1.B8

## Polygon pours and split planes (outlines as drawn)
GND on Top Layer "Top Layer-No Net" (solid, remove dead copper, pour order 5): 3240.49,4390 cw(c3243,4390) 3240.49,4390.02 3240.49,4391 cw(c3243,4391) 3240.51,4391.36 cw(c3302.5,4389.5) 3303.01,4451.52 cw(c3302.5,4389.5) 3303.02,4451.51 3303,4451.52 4360,4451.52 cw(c4360,4449) 4360.21,4451.51 cw(c4354.5,4383.5) 4422.75,4383.5 cw(c4354.5,4383.5) 4422.52,4377.9 4422.52,2031.01 cw(c4421,2029) 4423.52,2029 cw(c4421,2029) 4423.51,2028.79 cw(c4343.5,2035.5) 4336.9,1955.48 3323.21,1955.48 cw(c3323,1957.99) 3323.07,1955.48 cw(c3320.96,2035.24) 3241.27,2031.38 cw(c3243,2033.2) 3240.49,2033.2
GND on Bottom Layer "Bottom Layer-No Net" (solid, remove dead copper, pour order 6): 3240.49,4390 cw(c3243,4390) 3240.49,4390.02 3240.49,4391 cw(c3243,4391) 3240.51,4391.36 cw(c3302.5,4389.5) 3303.01,4451.52 cw(c3302.5,4389.5) 3303.02,4451.51 3303,4451.52 4360,4451.52 cw(c4360,4449) 4360.21,4451.51 cw(c4354.5,4383.5) 4422.75,4383.5 cw(c4354.5,4383.5) 4422.52,4377.9 4422.52,2031.01 cw(c4421,2029) 4423.52,2029 cw(c4421,2029) 4423.51,2028.79 cw(c4343.5,2035.5) 4336.9,1955.48 3323.21,1955.48 cw(c3323,1957.99) 3323.07,1955.48 cw(c3320.96,2035.24) 3241.27,2031.38 cw(c3243,2033.2) 3240.49,2033.2

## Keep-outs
Keep-Out Layer:
  lines w5: 3243,2033.2 3243,2223 3243,4391 ; 3243,4390 cw(c3302.5,4389.5) 3303,4449 4360,4449 cw(c4354.5,4383.5) 4420,4378 ; 3243.72,2033.2 ccw(c3320.96,2035.24) 3323,1957.99 ; 3322,1958 4347,1958 ; 4336,1958 ccw(c4342.5,2035.5) 4420,2029 4420,2238 ; 4420,2230 4420,4381

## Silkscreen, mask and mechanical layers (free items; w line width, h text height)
Top Overlay:
  text "VDD" at 4210,4380 h30
  text "GND" at 3375,4371 h30
  text "VDD" at 4002,4294 h30
  text "GND" at 3796,4293 h30
  text "DIO" at 3902,4293 h30
  text "RST" at 3594,4292 h30
  text "CLK" at 3696,4292 h30
  text "VDD" at 4211,4279 h30
  text "GND" at 3375,4273 h30
  text "GND" at 3979,4179 h30
  text "VDD" at 4212,4178 h30
  text "GND" at 3375,4174 h30
  text "PA10" at 4187,4083 h30
  text "PA11" at 3373,4076 h30
  text "BOOT0" at 3930,4065 h30
  text "PA9" at 4210,3977 h30
  text "PA12" at 3372,3974 h30
  text "VCC" at 3986,3963 h30
  text "PA8" at 4209,3883 h30
  text "PA13_SWDIO" at 3372,3874 h30
  text "VCC/PB2" at 4089,3784 h30
  text "PA14_SWCLK" at 3372,3771 h30
  text "GND" at 4210,3680 h30
  text "PA15" at 3372,3672 h30
  text "PB1" at 4221,3579 h30
  text "PB3" at 3372,3572 h30
  text "PB0" at 4211,3477 h30
  text "PB4" at 3373,3472 h30
  text "PA7" at 4210,3378 h30
  text "PB5" at 3373,3374 h30
  text "PA6" at 4211,3282 h30
  text "PB6" at 3373,3273 h30
  text "PA5" at 4210,3184 h30
  text "PB7" at 3371,3175 h30
  text "PA4" at 4212,3081 h30
  text "PF4_BOOT0" at 3371,3072 h30
  text "PA3" at 4209,2981 h30
  text "VSS/PB8" at 3374,2970 h30
  text "PA2" at 4210,2883 h30
  text "VDD" at 3376,2873 h30
  text "PA1" at 4221,2779 h30
  text "PF0_OSCIN" at 3372,2773 h30
  text "PA0" at 4210,2679 h30
  text "PF1_OSCOUT" at 3371,2673 h30
  text "PF3" at 4210.45,2582.02 h30
  text "RST" at 3373,2571 h30
  text "GND" at 4206,2479 h30
  text "GND" at 3376,2471 h30
  text "GND" at 4206,2379 h30
  text "GND" at 3375,2370 h30
  text "GND" at 4206,2278 h30
  text "GND" at 3375,2270 h30
Bottom Overlay:
  drawing of 448 lines, arcs and shapes, not listed
  text "WWW.PUYASEMI.COM" at 4098,3906 h40
  text "PY32F030_Start Kit V1.2" at 4102,3836 h40
  text "2022.05" at 4108,3764 h40
  text "SN:" at 4104,3690 h40

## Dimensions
3244,1972 to 4421,1982 on Mechanical 1
3256,4448 to 3267,1956 on Mechanical 1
